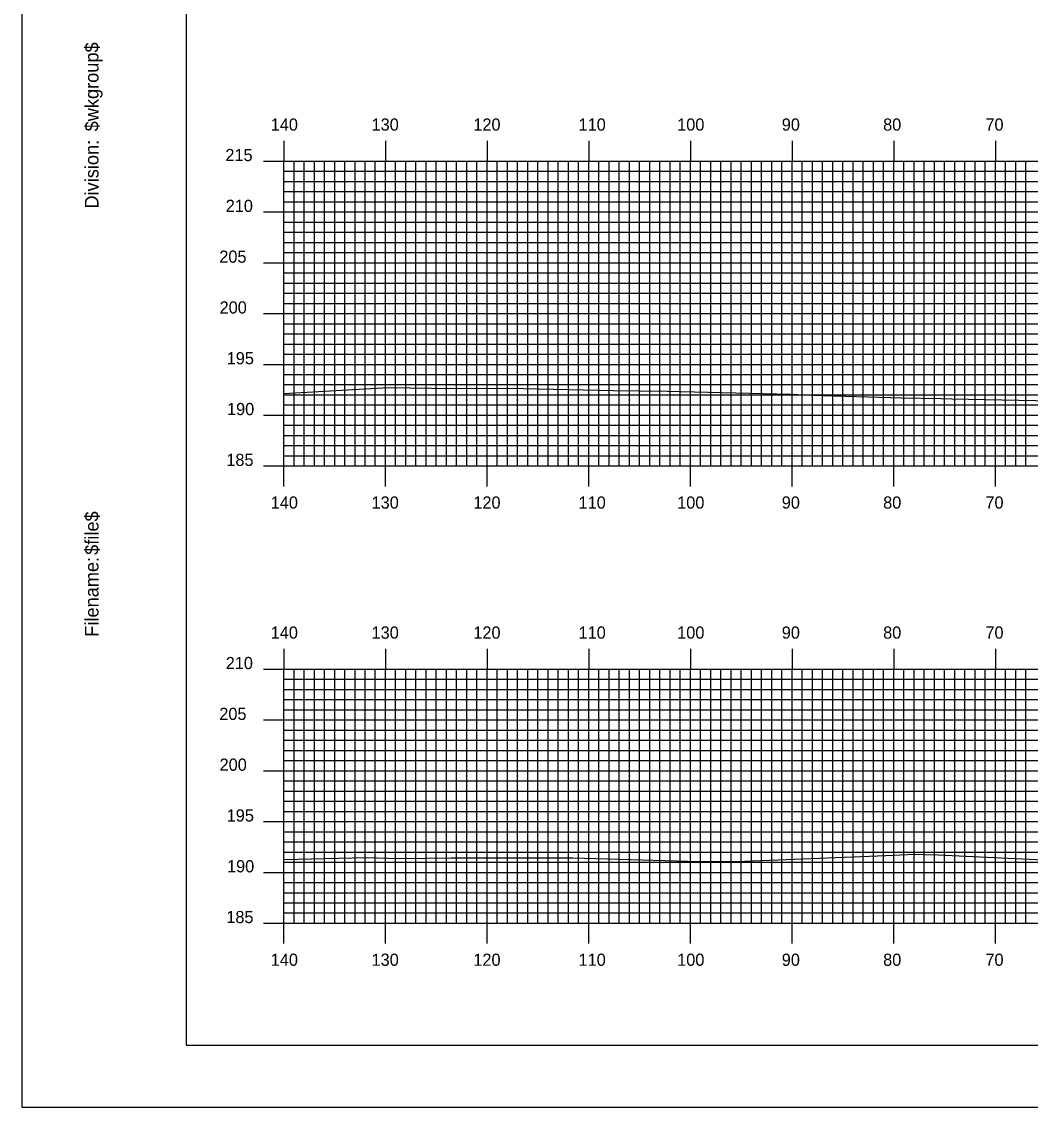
# Model space of a CAD drawing. Extents: x 1815309 to 1815652, y 442591 to 442811.
# Drawn here: x 1815308.7 to 1815408, y 442590.5 to 442697.4 of the extents above; entities that cross this region are included whole.
import ezdxf

# ---------------------------------------------------------------- set-up
doc = ezdxf.new("R2010")
doc.units = 0
for name, color, linetype in [('BORDER', 7, 'Continuous'), ('H_V ANNOTATION', 7, 'Continuous'), ('MAJOR', 7, 'Continuous'), ('MINOR', 7, 'Continuous'), ('PLOT BOUNDARY', 7, 'Continuous'), ('S_Roadway_Centerline', 7, 'Continuous')]:
    doc.layers.add(name, color=color, linetype=linetype)

msp = doc.modelspace()

# ---------------------------------------------------------------- linework, layer by layer
at = {"layer": 'BORDER'}
msp.add_lwpolyline([(1815324.93, 442596.67), (1815644.93, 442596.67), (1815644.93, 442806.67), (1815324.93, 442806.67)], close=True, dxfattribs=at)
at = {"layer": 'MAJOR'}
for p, q in [((1815334.53, 442685.67), (1815334.53, 442683.67)), ((1815344.53, 442685.67), (1815344.53, 442683.67)), ((1815354.53, 442685.67), (1815354.53, 442683.67)), ((1815364.53, 442685.67), (1815364.53, 442683.67)), ((1815374.53, 442685.67), (1815374.53, 442683.67)), ((1815384.53, 442685.67), (1815384.53, 442683.67)), ((1815394.53, 442685.67), (1815394.53, 442683.67)), ((1815404.53, 442685.67), (1815404.53, 442683.67)), ((1815332.53, 442683.67), (1815334.53, 442683.67)), ((1815334.53, 442683.67), (1815614.53, 442683.67)), ((1815334.53, 442653.67), (1815334.53, 442683.67)), ((1815334.53, 442653.67), (1815334.53, 442683.67)), ((1815334.53, 442683.67), (1815614.53, 442683.67)), ((1815344.53, 442653.67), (1815344.53, 442683.67)), ((1815354.53, 442653.67), (1815354.53, 442683.67)), ((1815364.53, 442653.67), (1815364.53, 442683.67)), ((1815374.53, 442653.67), (1815374.53, 442683.67)), ((1815384.53, 442653.67), (1815384.53, 442683.67)), ((1815394.53, 442653.67), (1815394.53, 442683.67)), ((1815404.53, 442653.67), (1815404.53, 442683.67)), ((1815332.53, 442678.67), (1815334.53, 442678.67)), ((1815334.53, 442678.67), (1815614.53, 442678.67)), ((1815332.53, 442673.67), (1815334.53, 442673.67)), ((1815334.53, 442673.67), (1815614.53, 442673.67)), ((1815332.53, 442668.67), (1815334.53, 442668.67)), ((1815334.53, 442668.67), (1815614.53, 442668.67)), ((1815332.53, 442663.67), (1815334.53, 442663.67)), ((1815334.53, 442663.67), (1815614.53, 442663.67)), ((1815332.53, 442658.67), (1815334.53, 442658.67)), ((1815334.53, 442658.67), (1815614.53, 442658.67)), ((1815332.53, 442653.67), (1815334.53, 442653.67)), ((1815334.53, 442653.67), (1815614.53, 442653.67)), ((1815334.53, 442653.67), (1815614.53, 442653.67)), ((1815334.53, 442651.66), (1815334.53, 442653.67)), ((1815344.53, 442651.66), (1815344.53, 442653.67)), ((1815354.53, 442651.66), (1815354.53, 442653.67)), ((1815364.53, 442651.66), (1815364.53, 442653.67)), ((1815374.53, 442651.66), (1815374.53, 442653.67)), ((1815384.53, 442651.66), (1815384.53, 442653.67)), ((1815394.53, 442651.66), (1815394.53, 442653.67)), ((1815404.53, 442651.66), (1815404.53, 442653.67)), ((1815334.53, 442635.67), (1815334.53, 442633.67)), ((1815344.53, 442635.67), (1815344.53, 442633.67)), ((1815354.53, 442635.67), (1815354.53, 442633.67)), ((1815364.53, 442635.67), (1815364.53, 442633.67)), ((1815374.53, 442635.67), (1815374.53, 442633.67)), ((1815384.53, 442635.67), (1815384.53, 442633.67)), ((1815394.53, 442635.67), (1815394.53, 442633.67)), ((1815404.53, 442635.67), (1815404.53, 442633.67)), ((1815332.53, 442633.67), (1815334.53, 442633.67)), ((1815334.53, 442633.67), (1815614.53, 442633.67)), ((1815334.53, 442608.67), (1815334.53, 442633.67)), ((1815334.53, 442608.67), (1815334.53, 442633.67)), ((1815334.53, 442633.67), (1815614.53, 442633.67)), ((1815344.53, 442608.67), (1815344.53, 442633.67)), ((1815354.53, 442608.67), (1815354.53, 442633.67)), ((1815364.53, 442608.67), (1815364.53, 442633.67)), ((1815374.53, 442608.67), (1815374.53, 442633.67)), ((1815384.53, 442608.67), (1815384.53, 442633.67)), ((1815394.53, 442608.67), (1815394.53, 442633.67)), ((1815404.53, 442608.67), (1815404.53, 442633.67)), ((1815332.53, 442628.67), (1815334.53, 442628.67)), ((1815334.53, 442628.67), (1815614.53, 442628.67)), ((1815332.53, 442623.67), (1815334.53, 442623.67)), ((1815334.53, 442623.67), (1815614.53, 442623.67)), ((1815332.53, 442618.67), (1815334.53, 442618.67)), ((1815334.53, 442618.67), (1815614.53, 442618.67)), ((1815332.53, 442613.67), (1815334.53, 442613.67)), ((1815334.53, 442613.67), (1815614.53, 442613.67)), ((1815332.53, 442608.67), (1815334.53, 442608.67)), ((1815334.53, 442608.67), (1815614.53, 442608.67)), ((1815334.53, 442608.67), (1815614.53, 442608.67)), ((1815334.53, 442606.66), (1815334.53, 442608.67)), ((1815344.53, 442606.66), (1815344.53, 442608.67)), ((1815354.53, 442606.66), (1815354.53, 442608.67)), ((1815364.53, 442606.66), (1815364.53, 442608.67)), ((1815374.53, 442606.66), (1815374.53, 442608.67)), ((1815384.53, 442606.66), (1815384.53, 442608.67)), ((1815394.53, 442606.66), (1815394.53, 442608.67)), ((1815404.53, 442606.66), (1815404.53, 442608.67))]:
    msp.add_line(p, q, dxfattribs=at)
at = {"layer": 'MINOR'}
for p, q in [((1815335.53, 442653.67), (1815335.53, 442683.67)), ((1815336.53, 442653.67), (1815336.53, 442683.67)), ((1815337.53, 442653.67), (1815337.53, 442683.67)), ((1815338.53, 442653.67), (1815338.53, 442683.67)), ((1815339.53, 442653.67), (1815339.53, 442683.67)), ((1815340.53, 442653.67), (1815340.53, 442683.67)), ((1815341.53, 442653.67), (1815341.53, 442683.67)), ((1815342.53, 442653.67), (1815342.53, 442683.67)), ((1815343.53, 442653.67), (1815343.53, 442683.67)), ((1815345.53, 442653.67), (1815345.53, 442683.67)), ((1815346.53, 442653.67), (1815346.53, 442683.67)), ((1815347.53, 442653.67), (1815347.53, 442683.67)), ((1815348.53, 442653.67), (1815348.53, 442683.67)), ((1815349.53, 442653.67), (1815349.53, 442683.67)), ((1815350.53, 442653.67), (1815350.53, 442683.67)), ((1815351.53, 442653.67), (1815351.53, 442683.67)), ((1815352.53, 442653.67), (1815352.53, 442683.67)), ((1815353.53, 442653.67), (1815353.53, 442683.67)), ((1815355.53, 442653.67), (1815355.53, 442683.67)), ((1815356.53, 442653.67), (1815356.53, 442683.67)), ((1815357.53, 442653.67), (1815357.53, 442683.67)), ((1815358.53, 442653.67), (1815358.53, 442683.67)), ((1815359.53, 442653.67), (1815359.53, 442683.67)), ((1815360.53, 442653.67), (1815360.53, 442683.67)), ((1815361.53, 442653.67), (1815361.53, 442683.67)), ((1815362.53, 442653.67), (1815362.53, 442683.67)), ((1815363.53, 442653.67), (1815363.53, 442683.67)), ((1815365.53, 442653.67), (1815365.53, 442683.67)), ((1815366.53, 442653.67), (1815366.53, 442683.67)), ((1815367.53, 442653.67), (1815367.53, 442683.67)), ((1815368.53, 442653.67), (1815368.53, 442683.67)), ((1815369.53, 442653.67), (1815369.53, 442683.67)), ((1815370.53, 442653.67), (1815370.53, 442683.67)), ((1815371.53, 442653.67), (1815371.53, 442683.67)), ((1815372.53, 442653.67), (1815372.53, 442683.67)), ((1815373.53, 442653.67), (1815373.53, 442683.67)), ((1815375.53, 442653.67), (1815375.53, 442683.67)), ((1815376.53, 442653.67), (1815376.53, 442683.67)), ((1815377.53, 442653.67), (1815377.53, 442683.67)), ((1815378.53, 442653.67), (1815378.53, 442683.67)), ((1815379.53, 442653.67), (1815379.53, 442683.67)), ((1815380.53, 442653.67), (1815380.53, 442683.67)), ((1815381.53, 442653.67), (1815381.53, 442683.67)), ((1815382.53, 442653.67), (1815382.53, 442683.67)), ((1815383.53, 442653.67), (1815383.53, 442683.67)), ((1815385.53, 442653.67), (1815385.53, 442683.67)), ((1815386.53, 442653.67), (1815386.53, 442683.67)), ((1815387.53, 442653.67), (1815387.53, 442683.67)), ((1815388.53, 442653.67), (1815388.53, 442683.67)), ((1815389.53, 442653.67), (1815389.53, 442683.67)), ((1815390.53, 442653.67), (1815390.53, 442683.67)), ((1815391.53, 442653.67), (1815391.53, 442683.67)), ((1815392.53, 442653.67), (1815392.53, 442683.67)), ((1815393.53, 442653.67), (1815393.53, 442683.67)), ((1815395.53, 442653.67), (1815395.53, 442683.67)), ((1815396.53, 442653.67), (1815396.53, 442683.67)), ((1815397.53, 442653.67), (1815397.53, 442683.67)), ((1815398.53, 442653.67), (1815398.53, 442683.67)), ((1815399.53, 442653.67), (1815399.53, 442683.67)), ((1815400.53, 442653.67), (1815400.53, 442683.67)), ((1815401.53, 442653.67), (1815401.53, 442683.67)), ((1815402.53, 442653.67), (1815402.53, 442683.67)), ((1815403.53, 442653.67), (1815403.53, 442683.67)), ((1815405.53, 442653.67), (1815405.53, 442683.67)), ((1815406.53, 442653.67), (1815406.53, 442683.67)), ((1815407.53, 442653.67), (1815407.53, 442683.67)), ((1815334.53, 442682.67), (1815614.53, 442682.67)), ((1815334.53, 442682.67), (1815336.54, 442682.67)), ((1815334.53, 442681.67), (1815614.53, 442681.67)), ((1815334.53, 442681.67), (1815336.54, 442681.67)), ((1815334.53, 442680.67), (1815614.53, 442680.67)), ((1815334.53, 442680.67), (1815336.54, 442680.67)), ((1815334.53, 442679.67), (1815614.53, 442679.67)), ((1815334.53, 442679.67), (1815336.54, 442679.67)), ((1815334.53, 442677.67), (1815614.53, 442677.67)), ((1815334.53, 442677.67), (1815336.54, 442677.67)), ((1815334.53, 442676.67), (1815614.53, 442676.67)), ((1815334.53, 442676.67), (1815336.54, 442676.67)), ((1815334.53, 442675.67), (1815614.53, 442675.67)), ((1815334.53, 442675.67), (1815336.54, 442675.67)), ((1815334.53, 442674.67), (1815614.53, 442674.67)), ((1815334.53, 442674.67), (1815336.54, 442674.67)), ((1815334.53, 442672.67), (1815614.53, 442672.67)), ((1815334.53, 442672.67), (1815336.54, 442672.67)), ((1815334.53, 442671.67), (1815614.53, 442671.67)), ((1815334.53, 442671.67), (1815336.54, 442671.67)), ((1815334.53, 442670.67), (1815614.53, 442670.67)), ((1815334.53, 442670.67), (1815336.54, 442670.67)), ((1815334.53, 442669.67), (1815614.53, 442669.67)), ((1815334.53, 442669.67), (1815336.54, 442669.67)), ((1815334.53, 442667.67), (1815614.53, 442667.67)), ((1815334.53, 442667.67), (1815336.54, 442667.67)), ((1815334.53, 442666.67), (1815614.53, 442666.67)), ((1815334.53, 442666.67), (1815336.54, 442666.67)), ((1815334.53, 442665.67), (1815614.53, 442665.67)), ((1815334.53, 442665.67), (1815336.54, 442665.67)), ((1815334.53, 442664.67), (1815614.53, 442664.67)), ((1815334.53, 442664.67), (1815336.54, 442664.67)), ((1815334.53, 442662.67), (1815614.53, 442662.67)), ((1815334.53, 442662.67), (1815336.54, 442662.67)), ((1815334.53, 442661.67), (1815614.53, 442661.67)), ((1815334.53, 442661.67), (1815336.54, 442661.67)), ((1815334.53, 442660.67), (1815614.53, 442660.67)), ((1815334.53, 442660.67), (1815336.54, 442660.67)), ((1815334.53, 442659.67), (1815614.53, 442659.67)), ((1815334.53, 442659.67), (1815336.54, 442659.67)), ((1815334.53, 442657.67), (1815614.53, 442657.67)), ((1815334.53, 442657.67), (1815336.54, 442657.67)), ((1815334.53, 442656.67), (1815614.53, 442656.67)), ((1815334.53, 442656.67), (1815336.54, 442656.67)), ((1815334.53, 442655.67), (1815614.53, 442655.67)), ((1815334.53, 442655.67), (1815336.54, 442655.67)), ((1815334.53, 442654.67), (1815614.53, 442654.67)), ((1815334.53, 442654.67), (1815336.54, 442654.67)), ((1815335.53, 442608.67), (1815335.53, 442633.67)), ((1815336.53, 442608.67), (1815336.53, 442633.67)), ((1815337.53, 442608.67), (1815337.53, 442633.67)), ((1815338.53, 442608.67), (1815338.53, 442633.67)), ((1815339.53, 442608.67), (1815339.53, 442633.67)), ((1815340.53, 442608.67), (1815340.53, 442633.67)), ((1815341.53, 442608.67), (1815341.53, 442633.67)), ((1815342.53, 442608.67), (1815342.53, 442633.67)), ((1815343.53, 442608.67), (1815343.53, 442633.67)), ((1815345.53, 442608.67), (1815345.53, 442633.67)), ((1815346.53, 442608.67), (1815346.53, 442633.67)), ((1815347.53, 442608.67), (1815347.53, 442633.67)), ((1815348.53, 442608.67), (1815348.53, 442633.67)), ((1815349.53, 442608.67), (1815349.53, 442633.67)), ((1815350.53, 442608.67), (1815350.53, 442633.67)), ((1815351.53, 442608.67), (1815351.53, 442633.67)), ((1815352.53, 442608.67), (1815352.53, 442633.67)), ((1815353.53, 442608.67), (1815353.53, 442633.67)), ((1815355.53, 442608.67), (1815355.53, 442633.67)), ((1815356.53, 442608.67), (1815356.53, 442633.67)), ((1815357.53, 442608.67), (1815357.53, 442633.67)), ((1815358.53, 442608.67), (1815358.53, 442633.67)), ((1815359.53, 442608.67), (1815359.53, 442633.67)), ((1815360.53, 442608.67), (1815360.53, 442633.67)), ((1815361.53, 442608.67), (1815361.53, 442633.67)), ((1815362.53, 442608.67), (1815362.53, 442633.67)), ((1815363.53, 442608.67), (1815363.53, 442633.67)), ((1815365.53, 442608.67), (1815365.53, 442633.67)), ((1815366.53, 442608.67), (1815366.53, 442633.67)), ((1815367.53, 442608.67), (1815367.53, 442633.67)), ((1815368.53, 442608.67), (1815368.53, 442633.67)), ((1815369.53, 442608.67), (1815369.53, 442633.67)), ((1815370.53, 442608.67), (1815370.53, 442633.67)), ((1815371.53, 442608.67), (1815371.53, 442633.67)), ((1815372.53, 442608.67), (1815372.53, 442633.67)), ((1815373.53, 442608.67), (1815373.53, 442633.67)), ((1815375.53, 442608.67), (1815375.53, 442633.67)), ((1815376.53, 442608.67), (1815376.53, 442633.67)), ((1815377.53, 442608.67), (1815377.53, 442633.67)), ((1815378.53, 442608.67), (1815378.53, 442633.67)), ((1815379.53, 442608.67), (1815379.53, 442633.67)), ((1815380.53, 442608.67), (1815380.53, 442633.67)), ((1815381.53, 442608.67), (1815381.53, 442633.67)), ((1815382.53, 442608.67), (1815382.53, 442633.67)), ((1815383.53, 442608.67), (1815383.53, 442633.67)), ((1815385.53, 442608.67), (1815385.53, 442633.67)), ((1815386.53, 442608.67), (1815386.53, 442633.67)), ((1815387.53, 442608.67), (1815387.53, 442633.67)), ((1815388.53, 442608.67), (1815388.53, 442633.67)), ((1815389.53, 442608.67), (1815389.53, 442633.67)), ((1815390.53, 442608.67), (1815390.53, 442633.67)), ((1815391.53, 442608.67), (1815391.53, 442633.67)), ((1815392.53, 442608.67), (1815392.53, 442633.67)), ((1815393.53, 442608.67), (1815393.53, 442633.67)), ((1815395.53, 442608.67), (1815395.53, 442633.67)), ((1815396.53, 442608.67), (1815396.53, 442633.67)), ((1815397.53, 442608.67), (1815397.53, 442633.67)), ((1815398.53, 442608.67), (1815398.53, 442633.67)), ((1815399.53, 442608.67), (1815399.53, 442633.67)), ((1815400.53, 442608.67), (1815400.53, 442633.67)), ((1815401.53, 442608.67), (1815401.53, 442633.67)), ((1815402.53, 442608.67), (1815402.53, 442633.67)), ((1815403.53, 442608.67), (1815403.53, 442633.67)), ((1815405.53, 442608.67), (1815405.53, 442633.67)), ((1815406.53, 442608.67), (1815406.53, 442633.67)), ((1815407.53, 442608.67), (1815407.53, 442633.67)), ((1815334.53, 442632.67), (1815614.53, 442632.67)), ((1815334.53, 442632.67), (1815336.54, 442632.67)), ((1815334.53, 442631.67), (1815614.53, 442631.67)), ((1815334.53, 442631.67), (1815336.54, 442631.67)), ((1815334.53, 442630.67), (1815614.53, 442630.67)), ((1815334.53, 442630.67), (1815336.54, 442630.67)), ((1815334.53, 442629.67), (1815614.53, 442629.67)), ((1815334.53, 442629.67), (1815336.54, 442629.67)), ((1815334.53, 442627.67), (1815614.53, 442627.67)), ((1815334.53, 442627.67), (1815336.54, 442627.67)), ((1815334.53, 442626.67), (1815614.53, 442626.67)), ((1815334.53, 442626.67), (1815336.54, 442626.67)), ((1815334.53, 442625.67), (1815614.53, 442625.67)), ((1815334.53, 442625.67), (1815336.54, 442625.67)), ((1815334.53, 442624.67), (1815614.53, 442624.67)), ((1815334.53, 442624.67), (1815336.54, 442624.67)), ((1815334.53, 442622.67), (1815614.53, 442622.67)), ((1815334.53, 442622.67), (1815336.54, 442622.67)), ((1815334.53, 442621.67), (1815614.53, 442621.67)), ((1815334.53, 442621.67), (1815336.54, 442621.67)), ((1815334.53, 442620.67), (1815614.53, 442620.67)), ((1815334.53, 442620.67), (1815336.54, 442620.67)), ((1815334.53, 442619.67), (1815614.53, 442619.67)), ((1815334.53, 442619.67), (1815336.54, 442619.67)), ((1815334.53, 442617.67), (1815614.53, 442617.67)), ((1815334.53, 442617.67), (1815336.54, 442617.67)), ((1815334.53, 442616.67), (1815614.53, 442616.67)), ((1815334.53, 442616.67), (1815336.54, 442616.67)), ((1815334.53, 442615.67), (1815614.53, 442615.67)), ((1815334.53, 442615.67), (1815336.54, 442615.67)), ((1815334.53, 442614.67), (1815614.53, 442614.67)), ((1815334.53, 442614.67), (1815336.54, 442614.67)), ((1815334.53, 442612.67), (1815614.53, 442612.67)), ((1815334.53, 442612.67), (1815336.54, 442612.67)), ((1815334.53, 442611.67), (1815614.53, 442611.67)), ((1815334.53, 442611.67), (1815336.54, 442611.67)), ((1815334.53, 442610.67), (1815614.53, 442610.67)), ((1815334.53, 442610.67), (1815336.54, 442610.67)), ((1815334.53, 442609.67), (1815614.53, 442609.67)), ((1815334.53, 442609.67), (1815336.54, 442609.67))]:
    msp.add_line(p, q, dxfattribs=at)
at = {"layer": 'PLOT BOUNDARY'}
msp.add_lwpolyline([(1815308.75, 442590.55), (1815648.75, 442590.55), (1815648.75, 442810.55), (1815308.75, 442810.55)], close=True, dxfattribs=at)
at = {"layer": 'S_Roadway_Centerline'}
for points in [[(1815334.53, 442660.81), (1815344.78, 442661.38), (1815349.06, 442661.32), (1815358.1, 442661.28), (1815366.94, 442661.11), (1815372.25, 442661.02), (1815384.36, 442660.75), (1815386.45, 442660.63), (1815395.33, 442660.38), (1815399.14, 442660.31), (1815400.23, 442660.28), (1815411.74, 442660.03)], [(1815334.53, 442614.95), (1815342.6, 442615.12), (1815345.88, 442615.04), (1815350.98, 442615.11), (1815362.95, 442615.1), (1815374.29, 442614.77), (1815379.01, 442614.74), (1815393.74, 442615.32), (1815396.61, 442615.46), (1815397.51, 442615.44), (1815398.89, 442615.41), (1815413.38, 442614.72)]]:
    msp.add_lwpolyline(points, dxfattribs=at)

# ---------------------------------------------------------------- texts
at = {"layer": 'BORDER'}
for s, p in [('$wkgroup$', (1815316.3, 442686.6)), ('Division:', (1815316.3, 442679)), ('$file$', (1815316.3, 442644.92)), ('Filename:', (1815316.3, 442636.86))]:
    msp.add_text(s, height=1.339, rotation=90, dxfattribs=at).set_placement(p)
at = {"layer": 'H_V ANNOTATION'}
for s, p in [('140', (1815333.24, 442686.67)), ('130', (1815343.16, 442686.67)), ('120', (1815353.17, 442686.67)), ('110', (1815363.52, 442686.67)), ('100', (1815373.22, 442686.67)), ('90', (1815383.51, 442686.67)), ('80', (1815393.48, 442686.67)), ('70', (1815403.54, 442686.67)), ('215', (1815328.78, 442683.67)), ('210', (1815328.81, 442678.67)), ('205', (1815328.18, 442673.67)), ('200', (1815328.21, 442668.67)), ('195', (1815328.91, 442663.67)), ('190', (1815328.94, 442658.67)), ('185', (1815328.87, 442653.67)), ('140', (1815333.24, 442649.47)), ('130', (1815343.16, 442649.47)), ('120', (1815353.17, 442649.47)), ('110', (1815363.52, 442649.47)), ('100', (1815373.22, 442649.47)), ('90', (1815383.51, 442649.47)), ('80', (1815393.48, 442649.47)), ('70', (1815403.54, 442649.47)), ('140', (1815333.24, 442636.67)), ('130', (1815343.16, 442636.67)), ('120', (1815353.17, 442636.67)), ('110', (1815363.52, 442636.67)), ('100', (1815373.22, 442636.67)), ('90', (1815383.51, 442636.67)), ('80', (1815393.48, 442636.67)), ('70', (1815403.54, 442636.67)), ('210', (1815328.81, 442633.67)), ('205', (1815328.18, 442628.67)), ('200', (1815328.21, 442623.67)), ('195', (1815328.91, 442618.67)), ('190', (1815328.94, 442613.67)), ('185', (1815328.87, 442608.67)), ('140', (1815333.24, 442604.47)), ('130', (1815343.16, 442604.47)), ('120', (1815353.17, 442604.47)), ('110', (1815363.52, 442604.47)), ('100', (1815373.22, 442604.47)), ('90', (1815383.51, 442604.47)), ('80', (1815393.48, 442604.47)), ('70', (1815403.54, 442604.47))]:
    msp.add_text(s, height=1.2, dxfattribs=at).set_placement(p)
at = {"layer": 'MAJOR'}
for p in [(1815334.52, 442653.67), (1815334.52, 442608.67)]:
    msp.add_text('-', height=0.012, dxfattribs=at).set_placement(p)

doc.saveas('drawing.dxf')
